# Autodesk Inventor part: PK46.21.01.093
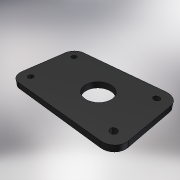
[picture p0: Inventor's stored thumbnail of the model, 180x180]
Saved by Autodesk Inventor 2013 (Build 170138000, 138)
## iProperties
Created: 2012-02
Part Number: PK46.21.01.093
Material: Rubber
Document SubType Name: Modeling
Designer: tedescj
Density: 0.93 g/cm^3
Mass: 191.134 g
Surface Area: 496.311 cm^2
Volume: 205.521 cm^3
Author: tedescj
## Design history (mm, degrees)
sketch "Sketch1"
  geometry: L1 (15, -5)-(165, -5); L2 (185, 15)-(185, 95); L3 (165, 115)-(15, 115); L4 (-5, 95)-(-5, 15); L5 (15, 95)-(165, 95); L6 (165, 95)-(165, 15); L7 (165, 15)-(15, 15); L8 (15, 15)-(15, 95); C1 r 5 at (15, 95); C2 r 5 at (15, 15); C3 r 5 at (165, 95); C4 r 5 at (165, 15); A1 r 20 centre (15, 95) between (15, 115) and (-5, 95); A2 r 20 centre (15, 15) between (-5, 15) and (15, -5); A3 r 20 centre (165, 15) between (165, -5) and (185, 15); A4 r 20 centre (165, 95) between (185, 95) and (165, 115); 1 further point
  constraints: 16 end point, 8 centre point, 8 point on circle, 7 coincident, 4 parallel, 4 tangent, 3 equal radius, 2 horizontal, 2 perpendicular
  dimensions: "d0" = 150 distance of L5.start L5.end; "d1" = 80 distance of L5.end L6.end; "d2" = 20 distance between parallel lines of L8 L4; "d3" = 20 distance between parallel lines of L2 L6; "d4" = 20 distance between parallel lines of L1 L7; "d5" = 20 distance between parallel lines of L5 L3; "d6" = 10 diameter of C1
extrude "Extrusion1" new body sketch "Sketch1" distance "d7" = 10; taper "d8" = 0 deg
hole "Hole1" diameter "d11" = 45; stored, may be unused: countersink angle "d15" = 90 deg, drill point angle "d17" = 118 deg; dims "d9" = 80, "d10" = 60, "d12" = 6, "d13" = 4, "d14" = 2, "d16" = 8
body "Solid1"
